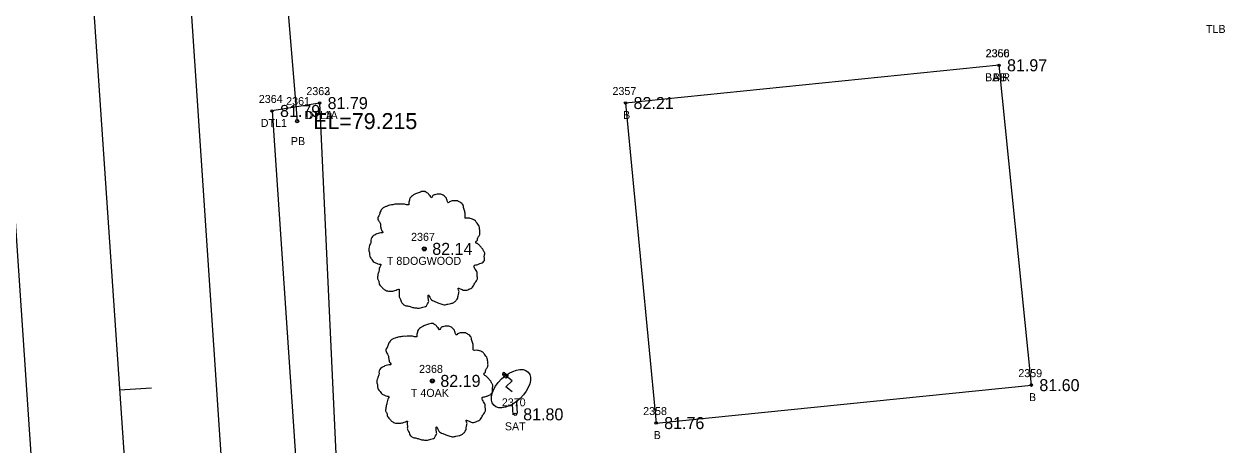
# Model space of a CAD drawing. Extents: x 2139392 to 2143384, y 505395 to 510520.
# Drawn here: x 2140601.5 to 2140751.6, y 507018.9 to 507071.5 of the extents above; entities that cross this region are included whole.
import ezdxf

# ---------------------------------------------------------------- set-up
doc = ezdxf.new("R2010")
doc.units = 0
for name, color, linetype in [('RD_EX_Bldg', 7, 'Continuous'), ('RD_EX_Bldg_txCode', 7, 'Continuous'), ('RD_EX_BldgApp', 7, 'Continuous'), ('RD_EX_BldgApp_txCode', 7, 'Continuous'), ('RD_EX_DR_Pipe', 7, 'Continuous'), ('RD_EX_DR_Pipe_txCode', 7, 'Continuous'), ('RD_EX_H2O', 7, 'Continuous'), ('RD_EX_H2O_txCode', 7, 'Continuous'), ('RD_EX_Road', 7, 'Continuous'), ('RD_EX_TX_Bldg_ELEV', 7, 'Continuous'), ('RD_EX_TX_BldgApp_ELEV', 7, 'Continuous'), ('RD_EX_TX_H2O_ELEV', 7, 'Continuous'), ('RD_EX_TX_VEG_ELEV', 7, 'Continuous'), ('RD_EX_VEG', 7, 'Continuous'), ('RD_EX_VEG_txCode', 7, 'Continuous'), ('RD_HC_Cl', 7, 'Continuous'), ('RD_HC_Data_Tic', 7, 'Continuous'), ('RD_SMD_Locator', 7, 'Continuous'), ('RD_TX_Pipe_ElevEX', 7, 'Continuous')]:
    doc.layers.add(name, color=color, linetype=linetype)

msp = doc.modelspace()

# ---------------------------------------------------------------- linework, layer by layer
at = {"layer": 'RD_EX_Bldg'}
msp.add_lwpolyline([(2140723.38, 507066.35), (2140676.7, 507061.63), (2140680.53, 507021.62), (2140727.42, 507026.36), (2140723.38, 507066.35)], dxfattribs=at)
at = {"layer": 'RD_EX_BldgApp'}
for p, q in [((2140661.74, 507027.24), (2140661.35, 507027.62)), ((2140662.53, 507026.92), (2140661.42, 507027.76)), ((2140661.59, 507027.92), (2140662.02, 507027.55)), ((2140661.63, 507027.66), (2140661.63, 507027.66)), ((2140661.74, 507027.64), (2140661.74, 507027.64)), ((2140662.02, 507027.55), (2140661.74, 507027.24)), ((2140661.76, 507026.15), (2140662.53, 507026.92)), ((2140662.53, 507025.54), (2140661.76, 507026.15)), ((2140662.53, 507023.98), (2140662.61, 507022.63)), ((2140663.07, 507024.26), (2140663.14, 507022.81))]:
    msp.add_line(p, q, dxfattribs=at)
msp.add_ellipse((2140662.38, 507025.92), major_axis=(-2.15, -2.07), ratio=0.564687, dxfattribs=at)
msp.add_ellipse((2140661.48, 507027.77), major_axis=(0.099, 0.164), ratio=0.846225, start_param=6.138676, end_param=9.218032, dxfattribs=at)
at = {"layer": 'RD_EX_DR_Pipe'}
msp.add_line((2140633.34, 507087.11), (2140635.66, 507059.37), dxfattribs=at)
at = {"layer": 'RD_EX_H2O'}
for points in [[(2140638.47, 507061.62), (2140632.52, 507060.64), (2140635.67, 507014.45), (2140647.45, 506911.43), (2140658.61, 506813.23)], [(2140638.47, 507061.62), (2140640.6, 507015.05), (2140655.91, 506912.54), (2140666.49, 506815.42)]]:
    msp.add_lwpolyline(points, dxfattribs=at)
at = {"layer": 'RD_EX_Road'}
for points in [[(2140583.43, 507730.59), (2140583.94, 507673.5), (2140583.85, 507666.58), (2140586.13, 507612.82), (2140586.39, 507606.18), (2140590.25, 507541.6), (2140593.48, 507494.33), (2140597.22, 507439.46), (2140604.83, 507331.21), (2140611.81, 507227.55), (2140614.04, 507200.36), (2140615.44, 507177.46), (2140615.82, 507170.81), (2140617.54, 507144.2), (2140618.8, 507126.38), (2140619.22, 507121.84), (2140620.89, 507096.21), (2140626.38, 507013.96)], [(2140559.74, 507699.59), (2140559.81, 507681.93), (2140560.3, 507666.18), (2140562.28, 507610.8), (2140566.4, 507547.54), (2140570.03, 507492.8), (2140573.82, 507437.38), (2140577.82, 507379.04), (2140579.38, 507354.44), (2140581.03, 507330.09), (2140587.99, 507226.36), (2140590.86, 507184.68), (2140593.07, 507153.16), (2140595.23, 507123.79), (2140602.7, 507012.79), (2140610.01, 506906.42), (2140617.09, 506803.24), (2140624.73, 506690.17), (2140631.76, 506586.09), (2140639.51, 506472.79), (2140646.1, 506374.38), (2140653.64, 506264.11)]]:
    msp.add_lwpolyline(points, dxfattribs=at)
at = {"layer": 'RD_EX_VEG'}
for centre, radius in [((2140651.55, 507043.4), 0.25), ((2140651.54, 507043.38), 0.0001), ((2140652.56, 507026.89), 0.25), ((2140652.54, 507026.87), 0.0001)]:
    msp.add_circle(centre, radius, dxfattribs=at)
for points in [[(2140651.68, 507050.57), (2140651.38, 507050.59), (2140651.06, 507050.49), (2140650.81, 507050.39), (2140650.58, 507050.32), (2140650.36, 507050.22), (2140650.06, 507050.04), (2140649.83, 507049.84), (2140649.71, 507049.59), (2140649.66, 507049.37), (2140649.61, 507049.09), (2140649.61, 507048.92), (2140649.48, 507048.89), (2140649.33, 507048.92), (2140649.08, 507048.99), (2140648.83, 507048.99), (2140648.58, 507048.99), (2140648.23, 507048.97), (2140647.88, 507048.97), (2140647.61, 507048.92), (2140647.28, 507048.87), (2140646.91, 507048.74), (2140646.56, 507048.62), (2140646.26, 507048.37), (2140646.01, 507047.89), (2140645.88, 507047.54), (2140645.73, 507047.29), (2140645.88, 507046.85), (2140646.06, 507046.5), (2140646.08, 507046.3), (2140646.16, 507045.87), (2140646.26, 507045.65), (2140646.38, 507045.45), (2140646.31, 507045.42), (2140645.93, 507045.37), (2140645.63, 507045.27), (2140645.21, 507045.05), (2140644.98, 507044.82), (2140644.88, 507044.5), (2140644.86, 507044.15), (2140644.76, 507043.95), (2140644.68, 507043.67), (2140644.66, 507043.6), (2140644.61, 507043.27), (2140644.71, 507042.82), (2140644.73, 507042.47), (2140644.86, 507042.25), (2140645.01, 507042.07), (2140645.18, 507041.82), (2140645.58, 507041.6), (2140645.91, 507041.5), (2140646.11, 507041.47), (2140645.93, 507040.97), (2140645.88, 507040.62), (2140645.76, 507040.22), (2140645.76, 507040.15), (2140645.71, 507039.67), (2140645.86, 507039.35), (2140645.93, 507038.97), (2140646.11, 507038.75), (2140646.38, 507038.45), (2140646.71, 507038.22), (2140647.21, 507038.1), (2140647.61, 507038.12), (2140648.18, 507038.3), (2140648.43, 507038.37), (2140648.41, 507038.2), (2140648.43, 507037.82), (2140648.43, 507037.4), (2140648.58, 507037.07), (2140648.68, 507036.8), (2140648.83, 507036.55), (2140649.16, 507036.32), (2140649.56, 507036.25), (2140649.98, 507036.1), (2140650.43, 507036.02), (2140650.93, 507036), (2140651.53, 507036.15), (2140651.81, 507036.27), (2140651.91, 507036.45), (2140652.11, 507036.82), (2140652.06, 507037.05), (2140652.08, 507037.65), (2140652.18, 507037.47), (2140652.36, 507037.12), (2140652.86, 507036.82), (2140653.26, 507036.65), (2140653.73, 507036.5), (2140654.03, 507036.42), (2140654.51, 507036.5), (2140654.88, 507036.57), (2140655.25, 507036.7), (2140655.55, 507036.97), (2140655.73, 507037.25), (2140655.78, 507037.52), (2140655.85, 507037.9), (2140655.9, 507038.07)], [(2140655.9, 507038.07), (2140655.83, 507038.25), (2140655.78, 507038.5), (2140655.85, 507038.47), (2140656.03, 507038.42), (2140656.3, 507038.3), (2140656.53, 507038.22), (2140656.85, 507038.25), (2140657.13, 507038.35), (2140657.58, 507038.62), (2140657.85, 507039.1), (2140658.13, 507039.5), (2140658.2, 507039.82), (2140658.15, 507040.05), (2140658.13, 507040.55), (2140657.93, 507040.8), (2140657.88, 507040.92), (2140657.78, 507041.32), (2140657.85, 507041.37), (2140658.13, 507041.42), (2140658.5, 507041.55), (2140658.78, 507041.67), (2140659, 507041.85), (2140659.08, 507042.07), (2140659.05, 507042.47), (2140659.1, 507042.87), (2140659.03, 507043.02), (2140658.93, 507043.17), (2140658.85, 507043.37), (2140658.7, 507043.52), (2140658.6, 507043.67), (2140658.5, 507043.77), (2140658.38, 507043.92), (2140658.2, 507044.05), (2140658.05, 507044.1), (2140658, 507044.25), (2140658.15, 507044.45), (2140658.2, 507044.55), (2140658.23, 507044.77), (2140658.45, 507045.12), (2140658.5, 507045.52), (2140658.45, 507045.95), (2140658.4, 507046.22), (2140658.25, 507046.5), (2140658.05, 507046.75), (2140657.93, 507046.92), (2140657.75, 507047.04), (2140657.43, 507047.17), (2140657.18, 507047.22), (2140656.83, 507047.22), (2140656.63, 507047.27), (2140656.65, 507047.32), (2140656.65, 507047.47), (2140656.65, 507047.74), (2140656.58, 507048.19), (2140656.43, 507048.69), (2140656.43, 507048.72), (2140656.33, 507048.97), (2140656.1, 507049.17), (2140655.93, 507049.27), (2140655.73, 507049.39), (2140655.48, 507049.42), (2140655.18, 507049.42), (2140654.91, 507049.37), (2140654.71, 507049.27), (2140654.53, 507049.14), (2140654.46, 507049.29), (2140654.36, 507049.59), (2140654.31, 507049.74), (2140654.16, 507049.92), (2140653.93, 507050.12), (2140653.48, 507050.24), (2140652.86, 507050.17), (2140652.56, 507049.97), (2140652.41, 507049.79), (2140652.36, 507049.92), (2140652.16, 507050.12), (2140652.06, 507050.29), (2140651.88, 507050.42), (2140651.73, 507050.52), (2140651.63, 507050.57)], [(2140652.69, 507034.06), (2140652.39, 507034.08), (2140652.06, 507033.98), (2140651.81, 507033.88), (2140651.59, 507033.81), (2140651.36, 507033.71), (2140651.06, 507033.53), (2140650.84, 507033.33), (2140650.71, 507033.08), (2140650.66, 507032.86), (2140650.61, 507032.58), (2140650.61, 507032.41), (2140650.49, 507032.38), (2140650.34, 507032.41), (2140650.09, 507032.48), (2140649.84, 507032.48), (2140649.59, 507032.48), (2140649.24, 507032.46), (2140648.89, 507032.46), (2140648.61, 507032.41), (2140648.29, 507032.36), (2140647.91, 507032.23), (2140647.57, 507032.11), (2140647.27, 507031.86), (2140647.02, 507031.38), (2140646.89, 507031.03), (2140646.74, 507030.78), (2140646.89, 507030.34), (2140647.07, 507029.99), (2140647.09, 507029.79), (2140647.17, 507029.36), (2140647.27, 507029.14), (2140647.39, 507028.94), (2140647.32, 507028.91), (2140646.94, 507028.86), (2140646.64, 507028.76), (2140646.22, 507028.54), (2140645.99, 507028.31), (2140645.89, 507027.99), (2140645.87, 507027.64), (2140645.77, 507027.44), (2140645.69, 507027.16), (2140645.67, 507027.09), (2140645.62, 507026.76), (2140645.72, 507026.31), (2140645.74, 507025.96), (2140645.87, 507025.74), (2140646.02, 507025.56), (2140646.19, 507025.31), (2140646.59, 507025.09), (2140646.92, 507024.99), (2140647.12, 507024.96), (2140646.94, 507024.46), (2140646.89, 507024.11), (2140646.77, 507023.71), (2140646.77, 507023.64), (2140646.72, 507023.16), (2140646.87, 507022.84), (2140646.94, 507022.46), (2140647.12, 507022.24), (2140647.39, 507021.94), (2140647.71, 507021.71), (2140648.21, 507021.59), (2140648.61, 507021.61), (2140649.19, 507021.79), (2140649.44, 507021.86), (2140649.41, 507021.69), (2140649.44, 507021.31), (2140649.44, 507020.89), (2140649.59, 507020.56), (2140649.69, 507020.29), (2140649.84, 507020.04), (2140650.16, 507019.81), (2140650.56, 507019.74), (2140650.99, 507019.59), (2140651.44, 507019.51), (2140651.94, 507019.49), (2140652.54, 507019.64), (2140652.81, 507019.76), (2140652.91, 507019.94), (2140653.11, 507020.31), (2140653.06, 507020.54), (2140653.09, 507021.14), (2140653.19, 507020.96), (2140653.36, 507020.61), (2140653.86, 507020.31), (2140654.26, 507020.14), (2140654.74, 507019.99), (2140655.04, 507019.91), (2140655.51, 507019.99), (2140655.89, 507020.06), (2140656.26, 507020.19), (2140656.56, 507020.46), (2140656.74, 507020.74), (2140656.79, 507021.01), (2140656.86, 507021.39), (2140656.91, 507021.56)], [(2140656.91, 507021.56), (2140656.84, 507021.74), (2140656.79, 507021.99), (2140656.86, 507021.96), (2140657.04, 507021.91), (2140657.31, 507021.79), (2140657.54, 507021.71), (2140657.86, 507021.74), (2140658.14, 507021.84), (2140658.59, 507022.11), (2140658.86, 507022.59), (2140659.13, 507022.99), (2140659.21, 507023.31), (2140659.16, 507023.54), (2140659.13, 507024.04), (2140658.94, 507024.29), (2140658.89, 507024.41), (2140658.79, 507024.81), (2140658.86, 507024.86), (2140659.13, 507024.91), (2140659.51, 507025.04), (2140659.78, 507025.16), (2140660.01, 507025.34), (2140660.08, 507025.56), (2140660.06, 507025.96), (2140660.11, 507026.36), (2140660.03, 507026.51), (2140659.93, 507026.66), (2140659.86, 507026.86), (2140659.71, 507027.01), (2140659.61, 507027.16), (2140659.51, 507027.26), (2140659.38, 507027.41), (2140659.21, 507027.54), (2140659.06, 507027.59), (2140659.01, 507027.74), (2140659.16, 507027.94), (2140659.21, 507028.04), (2140659.23, 507028.26), (2140659.46, 507028.61), (2140659.51, 507029.01), (2140659.46, 507029.44), (2140659.41, 507029.71), (2140659.26, 507029.99), (2140659.06, 507030.24), (2140658.94, 507030.41), (2140658.76, 507030.54), (2140658.44, 507030.66), (2140658.19, 507030.71), (2140657.84, 507030.71), (2140657.64, 507030.76), (2140657.66, 507030.81), (2140657.66, 507030.96), (2140657.66, 507031.23), (2140657.59, 507031.68), (2140657.44, 507032.18), (2140657.44, 507032.21), (2140657.34, 507032.46), (2140657.11, 507032.66), (2140656.94, 507032.76), (2140656.74, 507032.88), (2140656.49, 507032.91), (2140656.19, 507032.91), (2140655.91, 507032.86), (2140655.71, 507032.76), (2140655.54, 507032.63), (2140655.46, 507032.78), (2140655.36, 507033.08), (2140655.31, 507033.23), (2140655.16, 507033.41), (2140654.94, 507033.61), (2140654.49, 507033.73), (2140653.86, 507033.66), (2140653.56, 507033.46), (2140653.41, 507033.28), (2140653.36, 507033.41), (2140653.16, 507033.61), (2140653.06, 507033.78), (2140652.89, 507033.91), (2140652.74, 507034.01), (2140652.64, 507034.06)]]:
    msp.add_spline(points, degree=3, dxfattribs=at)
at = {"layer": 'RD_HC_Cl'}
msp.add_line((2140574.74, 507595.12), (2140664.08, 506281.81), dxfattribs=at)
at = {"layer": 'RD_HC_Data_Tic'}
msp.add_line((2140613.47, 507025.77), (2140617.46, 507026.04), dxfattribs=at)
at = {"layer": 'RD_SMD_Locator'}
for centre, radius in [((2140723.38, 507066.35), 0.15), ((2140723.38, 507066.35), 0.15), ((2140632.52, 507060.64), 0.15), ((2140638.47, 507061.62), 0.15), ((2140638.47, 507061.62), 0.15), ((2140676.7, 507061.63), 0.15), ((2140635.66, 507059.37), 0.2), ((2140651.55, 507043.4), 0.15), ((2140652.56, 507026.89), 0.15), ((2140727.42, 507026.36), 0.15), ((2140662.91, 507022.71), 0.15), ((2140680.53, 507021.62), 0.15)]:
    msp.add_circle(centre, radius, dxfattribs=at)

# ---------------------------------------------------------------- texts
at = {"layer": 'RD_EX_Bldg_txCode'}
for s, p in [('2360', (2140721.69, 507067.35)), ('2356', (2140721.73, 507067.35)), ('BA R', (2140721.63, 507064.35)), ('BB', (2140722.6, 507064.35)), ('2357', (2140675.07, 507062.63)), ('B', (2140676.39, 507059.63)), ('2359', (2140725.79, 507027.36)), ('B', (2140727.12, 507024.36)), ('2358', (2140678.9, 507022.62)), ('B', (2140680.22, 507019.62))]:
    msp.add_text(s, height=1, dxfattribs=at).set_placement(p)
at = {"layer": 'RD_EX_BldgApp_txCode'}
for s, p in [('2370', (2140661.24, 507023.71)), ('SAT', (2140661.62, 507020.71))]:
    msp.add_text(s, height=1, dxfattribs=at).set_placement(p)
at = {"layer": 'RD_EX_DR_Pipe_txCode'}
for s, p in [('2361', (2140634.29, 507061.37)), ('PB', (2140634.88, 507056.37))]:
    msp.add_text(s, height=1, dxfattribs=at).set_placement(p)
at = {"layer": 'RD_EX_H2O_txCode'}
for s, p in [('2362', (2140636.81, 507062.62)), ('2363', (2140636.81, 507062.62)), ('2364', (2140630.87, 507061.64)), ('DTL1A', (2140636.57, 507059.62)), ('DTLA', (2140636.73, 507059.62)), ('DTL1', (2140631.11, 507058.64))]:
    msp.add_text(s, height=1, dxfattribs=at).set_placement(p)
at = {"layer": 'RD_EX_TX_Bldg_ELEV'}
for s, p in [('81.97', (2140724.38, 507065.6)), ('81.97', (2140724.38, 507065.6)), ('82.21', (2140677.7, 507060.88)), ('81.60', (2140728.42, 507025.61)), ('81.76', (2140681.53, 507020.87))]:
    msp.add_text(s, height=1.5, dxfattribs=at).set_placement(p)
at = {"layer": 'RD_EX_TX_BldgApp_ELEV'}
msp.add_text('81.80', height=1.5, dxfattribs=at).set_placement((2140663.91, 507021.96))
at = {"layer": 'RD_EX_TX_H2O_ELEV'}
for p in [(2140639.47, 507060.87), (2140639.47, 507060.87), (2140633.52, 507059.89)]:
    msp.add_text('81.79', height=1.5, dxfattribs=at).set_placement(p)
at = {"layer": 'RD_EX_TX_VEG_ELEV'}
for s, p in [('82.14', (2140652.55, 507042.65)), ('82.19', (2140653.56, 507026.14))]:
    msp.add_text(s, height=1.5, dxfattribs=at).set_placement(p)
at = {"layer": 'RD_EX_VEG_txCode'}
for s, p in [('TLB', (2140749.24, 507070.39)), ('2367', (2140649.9, 507044.4)), ('T 8DOGWOOD', (2140646.87, 507041.4)), ('2368', (2140650.9, 507027.89)), ('T 4OAK', (2140649.87, 507024.89))]:
    msp.add_text(s, height=1, dxfattribs=at).set_placement(p)
at = {"layer": 'RD_TX_Pipe_ElevEX'}
msp.add_text('EL=79.215', height=2, dxfattribs=at).set_placement((2140637.66, 507058.37))

doc.saveas('drawing.dxf')
